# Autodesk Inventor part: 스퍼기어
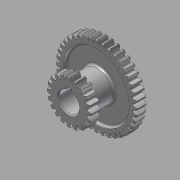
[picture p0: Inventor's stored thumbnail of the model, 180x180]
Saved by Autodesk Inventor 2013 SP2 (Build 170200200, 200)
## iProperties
Created: 2015-09
Part Number: 스퍼기어
Material: 강철, 연강
Document SubType Name: Modeling
Designer: mduedu
Density: 7.86 g/cm^3
Mass: 345.726 g
Surface Area: 225.641 cm^2
Volume: 43.9855 cm^3
Author: mduedu
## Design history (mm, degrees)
sketch "스케치1"
  geometry: C1 r 38 at (0, 0); C2 r 40 at (0, 0); C3 r 35.5 at (0, 0); 1 further point
  constraints: 3 centre point, 3 coincident
  dimensions: "d0" = 76 diameter of C1; "d2" = 2 radial gap between concentric circles of C2 C1; "d3" = 71 diameter of C3 (computed from d0)
extrude "돌출1" new body sketch "스케치1" stored distance "d4" = 10; taper "d5" = 0 deg
sketch "스케치2"
  geometry: L1 (0, 35.5)-(0, -35.5); L2 (0, 0)-(40, 0); L3 (0, 0.57)-(39.996, 0.57); L4 (0, 1.57)-(39.969, 1.57); L5 (0, 2.07)-(39.946, 2.07); A1 r 35.5 centre (0, 0) between (0, 35.5) and (0, -35.5) reference; A2 r 40 centre (0, 0) between (40, 0) and (39.946, 2.07) reference; A3 r 9.234 centre (34.93, -7.149) between (39.996, 0.57) and (35.44, 2.07); A4 r 9.234 centre (34.93, 7.149) between (35.44, -2.07) and (39.996, -0.57); A5 r 40 centre (0, 0) between (39.996, -0.57) and (39.996, 0.57); A6 r 35.5 centre (0, 0) between (35.44, -2.07) and (35.44, 2.07); 4 further points
  constraints: 16 point on circle, 10 end point, 6 point on line, 4 centre point, 3 coincident, 3 parallel, 3 symmetric about line, 2 midpoint, 1 perpendicular, 1 vertical, 3 other
  dimensions: "d6" = 0.5 distance between parallel lines of L4 L5; "d8" = 1 distance between parallel lines of L3 L4; "d9" = 1.57 distance between parallel lines of L2 L4
extrude "돌출2" join sketch "스케치2" distance "d10" = 5; taper "d12" = 0 deg; dims "d11" = 5, "d13" = 0
fillet "모깎기1" dims "d17" = 0.5
chamfer "모따기1" distance "d21" = 1; stored, may be unused: second distance "d22" = 2, angle "d23" = 45 deg
sketch "스케치3"
  geometry: C1 r 32.5 at (0, 0); C2 r 15 at (0, 0); 1 further point
  constraints: 2 centre point, 2 coincident
  dimensions: "d27" = 65 diameter of C1; "d28" = 30 diameter of C2
extrude "돌출3" cut sketch "스케치3" distance "d29" = 3; taper "d30" = 0 deg
fillet "모깎기2" dims "d31" = 2
node "작업 평면2"
  node "작업 평면1"
sketch "스케치4"
  geometry: C1 r 15 at (0, 0) reference; 1 further point
extrude "돌출4" join sketch "스케치4" stored distance "d34" = 3; taper "d35" = 0 deg
sketch "스케치5"
  geometry: C1 r 17.5 at (0, 0); C2 r 20 at (0, 0); C3 r 22 at (0, 0); 1 further point
  constraints: 3 centre point, 3 coincident
  dimensions: "d36" = 40 diameter of C2; "d38" = 2 radial gap between concentric circles of C2 C3; "d39" = 35 diameter of C1 (= d36 - 2.5 x d38)
extrude "돌출6" join sketch "스케치5" distance "d46" = 10; taper "d47" = 0 deg
sketch "스케치6"
  geometry: L1 (0, 0)-(0, 22); L2 (-17.5, 0)-(17.5, 0); L3 (-0.57, 0)-(-0.57, 21.993); L4 (-1.57, 0)-(-1.57, 21.944); L5 (-2.07, 0)-(-2.07, 21.902); A1 r 22 centre (0, 0) between (0, 22) and (-0.57, 21.993) reference; A2 r 17.5 centre (0, 0) between (-17.5, 0) and (17.5, 0) reference; A3 r 9.431 centre (7.348, 16.868) between (-0.57, 21.993) and (-2.07, 17.377); A4 r 9.431 centre (-7.348, 16.868) between (2.07, 17.377) and (0.57, 21.993); A5 r 17.5 centre (0, 0) between (2.07, 17.377) and (-2.07, 17.377); A6 r 22 centre (0, 0) between (0.57, 21.993) and (-0.57, 21.993); 4 further points
  constraints: 16 point on circle, 10 end point, 5 point on line, 4 centre point, 3 coincident, 3 symmetric about line, 2 parallel, 2 perpendicular, 1 midpoint, 1 vertical, 3 other
  dimensions: "d40" = 0.5 distance between parallel lines of L4 L5; "d42" = 1 distance between parallel lines of L3 L4; "d43" = 1.57 distance between parallel lines of L1 L4
extrude "돌출5" join sketch "스케치6" distance "d44" = 10; taper "d45" = 0 deg
fillet "모깎기3" dims "d48" = 0.5
chamfer "모따기2" distance "d49" = 1; stored, may be unused: second distance "d50" = 2, angle "d51" = 45 deg
sketch "스케치7"
  geometry: C1 r 10 at (0, 0); 1 further point
  constraints: 1 centre point, 1 coincident
  dimensions: "d55" = 20 diameter of C1
extrude "돌출7" cut sketch "스케치7" stored distance "d56" = 10; taper "d57" = 0 deg
sketch "스케치8"
  geometry: L1 (-9.539, -3)-(-12.8, -3); L2 (-12.8, -3)-(-12.8, 3); L3 (-12.8, 3)-(-9.539, 3); L4 (-9.539, 3)-(-9.539, -3); A1 r 10 centre (0, 0) between (-9.539, -3) and (-9.539, 3) reference; 2 further points
  constraints: 8 end point, 3 point on circle, 2 parallel, 1 horizontal, 1 horizontal alignment, 1 perpendicular
  dimensions: "d58" = 6 distance of L1.end L2.end; "d60" = 22.8 distance from line of point (10, 0) L2
extrude "돌출8" cut sketch "스케치8" stored distance "d61" = 10; taper "d62" = 0 deg
chamfer "모따기3" distance "d63" = 1; stored, may be unused: second distance "d64" = 2, angle "d65" = 45 deg
fillet "모깎기4" dims "d66" = 2
node "솔리드1"
pattern_circular "원형 패턴3" dims "d25" = 360 deg
mirror "대칭1"
pattern_circular "원형 패턴4" dims "d53" = 360 deg
other parameters: "d32" = 5, "d33" = 42
